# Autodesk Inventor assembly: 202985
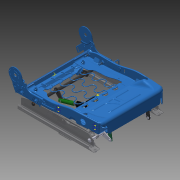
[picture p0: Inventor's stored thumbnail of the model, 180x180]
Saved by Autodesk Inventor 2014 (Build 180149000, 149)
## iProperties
Created: 2007-12
Part Number: 202985
Document SubType Name: Assembly
Designer: MM
Mass: 2360.19 g
Surface Area: 15768.9 cm^2
Volume: 1841.17 cm^3
Density: 1.2819 g/cm^3
Description: LOWER FULL ASSEMBLY
Component Category: Lower Component
Author: MM
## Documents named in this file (20)
- C:\Users\iTools\Desktop\tutorial files\Automotive\2000\202985.iam
- C:\Users\iTools\Desktop\tutorial files\Automotive\2000\200363.iam
- C:\Users\iTools\Desktop\tutorial files\Automotive\2000\201535.iam
- C:\Users\iTools\Desktop\tutorial files\Automotive\2000\200685.iam
- C:\Users\iTools\Desktop\tutorial files\Automotive\2000\200835.iam
- C:\Users\iTools\Desktop\tutorial files\Automotive\2000\200347.ipt
- C:\Users\iTools\Desktop\tutorial files\Automotive\8000\800463.ipt
- C:\Users\iTools\Desktop\tutorial files\Automotive\2000\201548.ipt
- C:\Users\iTools\Desktop\tutorial files\Automotive\2000\200333.ipt
- C:\Users\iTools\Desktop\tutorial files\Automotive\9000\900404.iam
- C:\Users\iTools\Desktop\tutorial files\Automotive\2000\201872.ipt
- C:\Users\iTools\Desktop\tutorial files\Automotive\2000\201661.ipt
- C:\Users\iTools\Desktop\tutorial files\Automotive\8000\801264.ipt
- C:\Users\iTools\Desktop\tutorial files\Automotive\8000\800025.ipt
- C:\Users\iTools\Desktop\tutorial files\Automotive\2000\200688.ipt
- C:\Users\iTools\Desktop\tutorial files\Automotive\2000\200489.ipt
- C:\Users\iTools\Desktop\tutorial files\Automotive\2000\200439.iam
- C:\Users\iTools\Desktop\tutorial files\Automotive\2000\200438.iam
- C:\Users\iTools\Desktop\tutorial files\Automotive\2000\200982.iam
- C:\Users\iTools\Desktop\tutorial files\Automotive\2000\200666.ipt
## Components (30 placed, 19 different names)
1. 200363:1 [sub-assembly] — Flush:1, Flush:2, Mate:23, Mate:24
2. 201535:1 [sub-assembly] — Flush:1, Flush:2, Mate:1, Mate:4, Insert:16, Mate:42
3. 200982:1 [sub-assembly] — Flush:3, Mate:1, Mate:21, Mate:22, Mate:25, Mate:43, Mate:45, Mate:47, Mate:49
4. 200685:1 [sub-assembly] — Flush:4, Mate:4, Mate:5, Mate:13, Flush:8, Mate:40
5. 200835:1 [sub-assembly] — Flush:5, Mate:5, Insert:6, Mate:28, Insert:9, Insert:10, Insert:11, Mate:29, Insert:14, Insert:15, Mate:51
6. 200347:1 — Mate:14, Mate:15, Mate:41, Tangent:1, Mate:43
7. 200347:2 — Mate:13, Flush:8, Mate:39, Mate:40
8. 800463:1 — Mate:14, Mate:15, Tangent:1
9. 201548:1 — Mate:21, Insert:3, Insert:5
10. 201548:2 — Mate:22, Insert:4
11. 200333:1 — Insert:3, Mate:23
12. 200333:2 — Insert:4, Mate:24
13. 900404:1 [sub-assembly] — Mate:25, Mate:26, Mate:27
14. 201872:1 — Insert:5, Mate:27
15. 201661:1 — Insert:6, Mate:28, Insert:7, Insert:8, Mate:32, Angle:5
16. 801264:1 — Insert:7
17. 801264:2 — Insert:8
18. 800025:1 — Insert:9
19. 800025:2 — Insert:10
20. 200688:1 — Insert:11, Mate:29, Insert:12, Insert:13, Mate:30, Angle:4, Mate:31
21. 801264:3 — Insert:13
22. 801264:4 — Insert:12
23. 800025:3 — Insert:15
24. 800025:4 — Insert:14
25. 200489:1 — Mate:30, Angle:4, Mate:31, Mate:33
26. 200489:2 — Mate:32, Angle:5, Mate:33
27. 200439:1 [sub-assembly] — Mate:41, Insert:16, Mate:42
28. 200438:1 [sub-assembly] — Mate:39
29. 200666:1 — Mate:45
30. 200666:2 — Mate:47, Mate:49, Mate:51
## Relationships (51: Mate 28, Insert 14, Flush 6, Angle 2, Tangent 1)
- Flush:1: 200363:1 ↔ 201535:1
- Flush:2: 200363:1 ↔ 201535:1
- Flush:3: 200982:1
- Mate:1: 201535:1 ↔ 200982:1
- Flush:4: 200685:1
- Mate:4: 201535:1 ↔ 200685:1
- Flush:5: 200835:1
- Mate:5: 200685:1 ↔ 200835:1
- Mate:13: 200685:1 ↔ 200347:2
- Flush:8: 200685:1 ↔ 200347:2
- Mate:14: 200347:1 ↔ 800463:1
- Mate:15: 200347:1 ↔ 800463:1
- Mate:21: 200982:1 ↔ 201548:1
- Mate:22: 200982:1 ↔ 201548:2
- Insert:3: 201548:1 ↔ 200333:1
- Insert:4: 201548:2 ↔ 200333:2
- Mate:23: 200363:1 ↔ 200333:1
- Mate:24: 200363:1 ↔ 200333:2
- Mate:25: 200982:1 ↔ 900404:1
- Insert:5: 201548:1 ↔ 201872:1
- Mate:26: 900404:1
- Mate:27: 900404:1 ↔ 201872:1
- Insert:6: 200835:1 ↔ 201661:1
- Mate:28: 200835:1 ↔ 201661:1
- Insert:7: 201661:1 ↔ 801264:1
- Insert:8: 201661:1 ↔ 801264:2
- Insert:9: 200835:1 ↔ 800025:1
- Insert:10: 200835:1 ↔ 800025:2
- Insert:11: 200835:1 ↔ 200688:1
- Mate:29: 200835:1 ↔ 200688:1
- Insert:12: 200688:1 ↔ 801264:4
- Insert:13: 200688:1 ↔ 801264:3
- Insert:14: 200835:1 ↔ 800025:4
- Insert:15: 200835:1 ↔ 800025:3
- Mate:30: 200688:1 ↔ 200489:1
- Angle:4: 200688:1 ↔ 200489:1
- Mate:31: 200688:1 ↔ 200489:1
- Mate:32: 201661:1 ↔ 200489:2
- Angle:5: 201661:1 ↔ 200489:2
- Mate:33: 200489:1 ↔ 200489:2
- Mate:41: 200347:1 ↔ 200439:1
- Insert:16: 201535:1 ↔ 200439:1
- Mate:39: 200347:2 ↔ 200438:1
- Mate:40: 200685:1 ↔ 200347:2
- Mate:42: 201535:1 ↔ 200439:1
- Tangent:1: 200347:1 ↔ 800463:1
- Mate:43: 200982:1 ↔ 200347:1
- Mate:45: 200982:1 ↔ 200666:1
- Mate:47: 200982:1 ↔ 200666:2
- Mate:49: 200982:1 ↔ 200666:2
- Mate:51: 200835:1 ↔ 200666:2
